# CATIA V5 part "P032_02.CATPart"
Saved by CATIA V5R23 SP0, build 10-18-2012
Part number: 05-LICP-T02-E-S03-P032_02
Bounding box of the stored display mesh (mm): x 0 to 21, y -11.997 to 12, z -11.997 to 11.997
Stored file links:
  C:\wamp\www\COURS\CONCEPTION GMP1\TITRE 02-SEMESTRE 2\03-TP7-PRESSE MECANIQUE\eleve\P032_02.CATPart
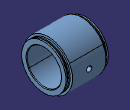
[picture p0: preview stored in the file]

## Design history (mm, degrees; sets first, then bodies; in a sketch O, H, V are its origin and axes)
Set1
  Point1: type Center, Curve edge [face of Solid1 | face of Solid1]
  Plane1: type OffsetPt, RefPlane yz-plane, RefPoint Point1
Body1 (main body)
  Solid1: solid without history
